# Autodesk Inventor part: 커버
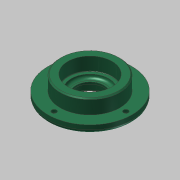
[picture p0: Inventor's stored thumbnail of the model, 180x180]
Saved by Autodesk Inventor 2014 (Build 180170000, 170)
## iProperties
Company: 한국ATC센터
Created: 2016-04
Part Number: 커버
Document SubType Name: Modeling
Designer: mdu
Density: 7.86 g/cm^3
Mass: 351.567 g
Surface Area: 161.165 cm^2
Volume: 44.7286 cm^3
Material: 강철, 연강
Appearance: 강철
Author: mdu
Revision Number: 1
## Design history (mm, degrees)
sketch "스케치1"
  geometry: C1 r 38 at (0, 0); 1 further point
  constraints: 1 centre point, 1 coincident
  dimensions: "d0" = 76 diameter of C1
extrude "돌출1" new body sketch "스케치1" distance "d1" = 7; taper "d2" = 0 deg
sketch "스케치2"
  geometry: C1 r 27 at (0, 0); 1 further point
  constraints: 1 centre point, 1 coincident
  dimensions: "d3" = 54 diameter of C1
extrude "돌출2" join sketch "스케치2" distance "d4" = 13; taper "d5" = 0 deg
sketch "스케치3"
  geometry: C1 r 20 at (0, 0); 1 further point
  constraints: 1 centre point, 1 coincident
  dimensions: "d6" = 40 diameter of C1
extrude "돌출3" join sketch "스케치3" distance "d7" = 5; taper "d8" = 0 deg
hole "구멍1" diameter "d11" = 25; stored, may be unused: countersink angle "d15" = 90 deg, drill point angle "d17" = 118 deg; dims "d9" = 10, "d10" = 10, "d12" = 6, "d13" = 32, "d14" = 8.3, "d16" = 8
hole "구멍2" diameter "d20" = 34; stored, may be unused: countersink angle "d24" = 90 deg, drill point angle "d26" = 0 deg; dims "d18" = 10, "d19" = 10, "d21" = 6, "d22" = 40, "d23" = 12, "d25" = 3
fillet "모깎기2" dims "d34" = 3
fillet "모깎기1" dims "d27" = 0.3
chamfer "모따기1" distance "d28" = 1; stored, may be unused: second distance "d29" = 2, angle "d30" = 45 deg
chamfer "모따기2" distance "d31" = 1.2; stored, may be unused: second distance "d32" = 2, angle "d33" = 30 deg
sketch "스케치4" dims "d35" = 65
  geometry: 3 further points
  constraints: 2 horizontal alignment, 1 coincident, 2 other
hole "구멍3" sketch "스케치4" at (32.5, 0) diameter "d36" = 4.5; stored, may be unused: countersink angle "d40" = 90 deg, drill point angle "d42" = 118 deg; dims "d37" = 6, "d38" = 8, "d39" = 4.4, "d41" = 13
node "솔리드1"
pattern_circular "원형 패턴1" dims angle "d44" = 360 deg
